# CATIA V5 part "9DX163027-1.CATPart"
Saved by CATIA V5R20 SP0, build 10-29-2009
Part number: 9DX163027-1
Revision: ANY
Definition: UNKNOWN
Nomenclature: 9DX163027-1
Source: Unknown
Bounding box of the stored display mesh (mm): x 0 to 314, y -8.99 to 8.99, z -8 to 9
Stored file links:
  C:\Users\Utente\Desktop\IO LAVORO\3D X SITO CF\CUMSA\3D files DX\DX 163027\9DX163027-1.CATPart
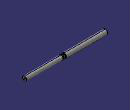
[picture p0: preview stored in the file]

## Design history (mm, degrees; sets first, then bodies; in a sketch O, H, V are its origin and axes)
Body1 "Redondeo1" (main body)
  Solid1: solid without history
